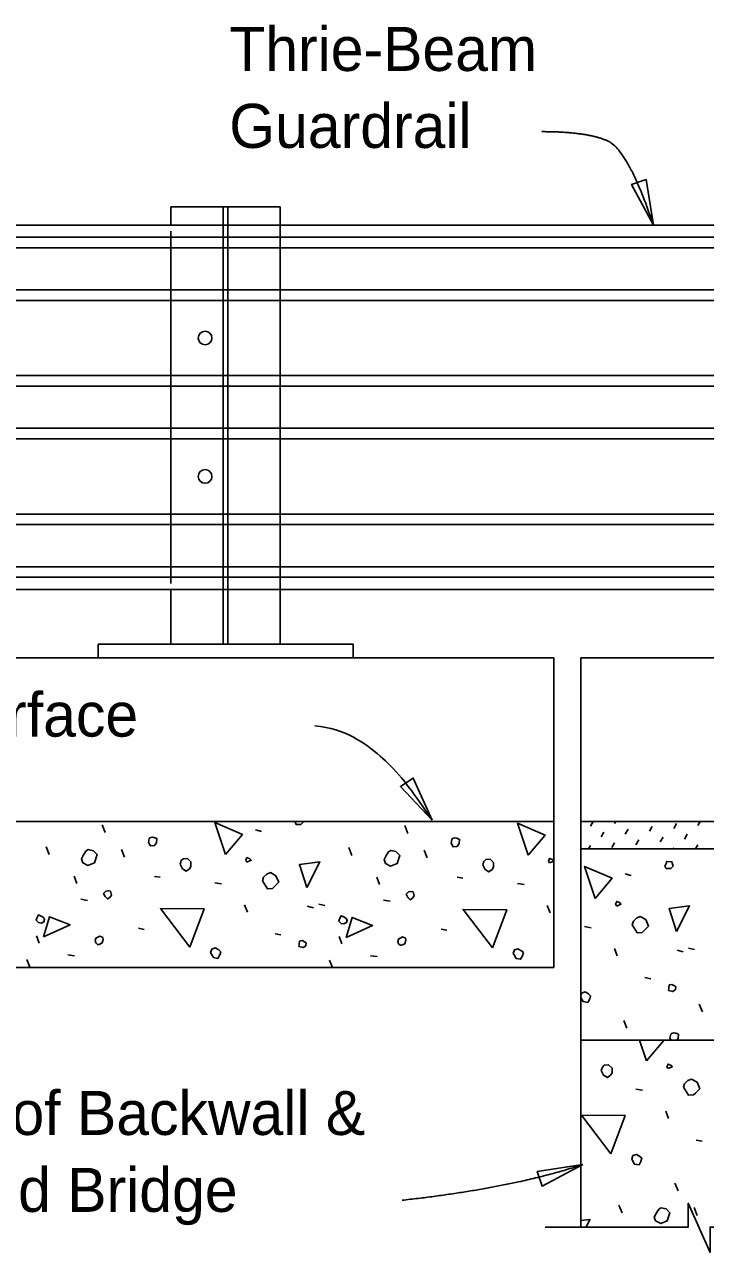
# Model space of a CAD drawing. Extents: x 21587 to 21659.1, y 56116.2 to 56157.3.
# Drawn here: x 21591.41 to 21594.53, y 56132.08 to 56137.7 of the extents above; entities that cross this region are included whole.
import ezdxf

# ---------------------------------------------------------------- set-up
doc = ezdxf.new("R2010")
doc.units = 0
for name, color, linetype in [('AdhocPoint_dp', 7, 'Continuous'), ('Border', 7, 'Continuous'), ('Patterning', 7, 'Continuous'), ('PlotBorder_dp', 7, 'Continuous'), ('SheetBorder_dp', 7, 'Continuous'), ('TextMisc', 7, 'Continuous')]:
    doc.layers.add(name, color=color, linetype=linetype)

msp = doc.modelspace()

# ---------------------------------------------------------------- linework, layer by layer
at = {"layer": 'AdhocPoint_dp'}
for p, q in [((21593.837, 56134.8009), (21587.6633, 56134.8009)), ((21593.837, 56134.8009), (21593.837, 56133.3842)), ((21593.9596, 56134.801), (21593.9596, 56132.1963)), ((21593.9596, 56134.8009), (21601.9067, 56134.8009)), ((21587.6633, 56134.0511), (21593.837, 56134.0511)), ((21604.323, 56134.0511), (21593.9596, 56134.0511)), ((21593.9596, 56133.926), (21604.323, 56133.926)), ((21587.6633, 56133.3843), (21593.837, 56133.3843)), ((21594.9595, 56133.051), (21593.9595, 56133.051))]:
    msp.add_line(p, q, dxfattribs=at)
at = {"layer": 'Border'}
for p, q in [((21592.0846, 56136.8635), (21592.5846, 56136.8635)), ((21592.0846, 56136.8635), (21592.0846, 56136.7802)), ((21592.5846, 56136.8635), (21592.5846, 56136.7802)), ((21599.7592, 56136.7801), (21587.6633, 56136.7801)), ((21587.6633, 56136.7246), (21599.7592, 56136.7246)), ((21587.6633, 56136.6764), (21599.7592, 56136.6764)), ((21587.6633, 56136.4835), (21599.7592, 56136.4835)), ((21587.6633, 56136.4353), (21599.7592, 56136.4353)), ((21587.6633, 56136.0914), (21599.7592, 56136.0914)), ((21587.6633, 56136.0431), (21599.7592, 56136.0431)), ((21587.6633, 56135.8503), (21599.7592, 56135.8503)), ((21587.6633, 56135.8022), (21599.7592, 56135.8022)), ((21587.6633, 56135.4582), (21599.7592, 56135.4582)), ((21587.6633, 56135.41), (21599.7592, 56135.41)), ((21587.6633, 56135.2172), (21599.7592, 56135.2172)), ((21587.6633, 56135.169), (21599.7592, 56135.169)), ((21599.7592, 56135.1134), (21587.6633, 56135.1134)), ((21592.0846, 56135.1135), (21592.0846, 56134.8635)), ((21592.5846, 56135.1134), (21592.5846, 56134.8635)), ((21591.7513, 56134.8635), (21592.9179, 56134.8635)), ((21591.7513, 56134.801), (21591.7513, 56134.8635)), ((21592.0846, 56134.8635), (21592.5846, 56134.8635)), ((21592.9179, 56134.8635), (21592.9179, 56134.801)), ((21591.7513, 56134.801), (21592.9179, 56134.801))]:
    msp.add_line(p, q, dxfattribs=at)
for centre in [(21592.2409, 56136.2634), (21592.2409, 56135.6303)]:
    msp.add_circle(centre, 0.0312, dxfattribs=at)
at = {"layer": 'Patterning'}
for p, q in [((21592.3242, 56134.8635), (21592.3242, 56136.8635)), ((21592.345, 56134.8635), (21592.345, 56136.8635)), ((21592.0846, 56136.7516), (21592.0846, 56135.1398)), ((21592.5846, 56136.7801), (21592.5846, 56135.1134))]:
    msp.add_line(p, q, dxfattribs=at)
at = {"layer": 'PlotBorder_dp'}
for points in [[(21594.2918, 56136.7795), (21594.2594, 56136.9882), (21594.1925, 56136.9659)], [(21593.2795, 56134.0576), (21593.193, 56134.2503), (21593.1343, 56134.2111)], [(21593.9695, 56132.4823), (21593.7607, 56132.4504), (21593.7829, 56132.3835)]]:
    msp.add_lwpolyline(points, close=True, dxfattribs=at)
msp.add_lwpolyline([(21595.248, 56132.1964), (21594.551, 56132.1964), (21594.551, 56132.0802), (21594.4516, 56132.3052), (21594.4516, 56132.1964), (21593.7964, 56132.1964)], dxfattribs=at)
for points, degree in [([(21593.7817, 56137.2074), (21593.9846, 56137.2074), (21594.1766, 56137.1251), (21594.2918, 56136.7795)], 2), ([(21592.7426, 56134.4896), (21592.8844, 56134.4753), (21593.0613, 56134.3451), (21593.1587, 56134.2379), (21593.2794, 56134.0575)], 3), ([(21593.9695, 56132.4824), (21593.6416, 56132.3739), (21593.1426, 56132.319)], 2)]:
    msp.add_open_spline(points, degree=degree, dxfattribs=at)
at = {"layer": 'TextMisc'}
for p, q in [((21594.004, 56134.0297), (21594.0163, 56134.0511)), ((21594.1146, 56134.0427), (21594.1194, 56134.0511)), ((21594.3847, 56134.0198), (21594.3976, 56134.0422)), ((21594.4953, 56134.0328), (21594.5059, 56134.0511)), ((21591.7845, 56134.0008), (21591.7703, 56134.0362)), ((21592.4709, 56134.0132), (21592.4992, 56134.0061)), ((21593.1691, 56133.9973), (21593.155, 56134.0326)), ((21594.0528, 56133.9809), (21594.0658, 56134.0033)), ((21594.1634, 56133.9939), (21594.1764, 56134.0163)), ((21594.2741, 56134.0068), (21594.287, 56134.0292)), ((21594.3229, 56133.958), (21594.3359, 56133.9804)), ((21594.4335, 56133.971), (21594.4465, 56133.9933)), ((21591.5281, 56133.9), (21591.514, 56133.9354)), ((21592.9128, 56133.8965), (21592.8987, 56133.9319)), ((21593.995, 56133.926), (21594.004, 56133.9415)), ((21594.1016, 56133.9321), (21594.1146, 56133.9545)), ((21594.2123, 56133.945), (21594.2252, 56133.9674)), ((21594.3815, 56133.926), (21594.3847, 56133.9315)), ((21594.4846, 56133.926), (21594.4953, 56133.9445)), ((21591.8722, 56133.8883), (21591.8581, 56133.9237)), ((21593.2569, 56133.8848), (21593.2428, 56133.9201)), ((21594.1625, 56133.8122), (21594.1907, 56133.8051)), ((21591.6536, 56133.7675), (21591.6413, 56133.801)), ((21592.0101, 56133.7999), (21592.0349, 56133.7964)), ((21592.2859, 56133.7716), (21592.3159, 56133.7663)), ((21593.0383, 56133.7639), (21593.026, 56133.7975)), ((21593.3948, 56133.7964), (21593.4195, 56133.7928)), ((21593.6706, 56133.7681), (21593.7006, 56133.7628)), ((21591.6725, 56133.6956), (21591.7025, 56133.6903)), ((21592.4344, 56133.6373), (21592.422, 56133.6709)), ((21592.7084, 56133.6638), (21592.7367, 56133.6567)), ((21592.7608, 56133.6738), (21592.7891, 56133.6667)), ((21593.0571, 56133.6921), (21593.0872, 56133.6868)), ((21593.8191, 56133.6337), (21593.8067, 56133.6673)), ((21591.9359, 56133.563), (21591.9624, 56133.5577)), ((21592.5617, 56133.5383), (21592.5882, 56133.533)), ((21593.3205, 56133.5595), (21593.3471, 56133.5542)), ((21593.9775, 56133.5707), (21594.0075, 56133.5654)), ((21591.4822, 56133.4947), (21591.4698, 56133.5283)), ((21592.8669, 56133.4912), (21592.8545, 56133.5248)), ((21591.4397, 56133.3851), (21591.4256, 56133.4205)), ((21591.6124, 56133.4411), (21591.6442, 56133.4375)), ((21592.997, 56133.4375), (21593.0289, 56133.434)), ((21594.126, 56133.4363), (21594.1136, 56133.4699)), ((21594.4, 56133.4628), (21594.4282, 56133.4558)), ((21594.4524, 56133.4728), (21594.4806, 56133.4657)), ((21592.8233, 56133.3843), (21592.8103, 56133.4169)), ((21594.2532, 56133.3373), (21594.2797, 56133.332)), ((21594.516, 56133.1806), (21594.5019, 56133.216)), ((21594.1701, 56133.1057), (21594.156, 56133.1411)), ((21593.9595, 56132.8522), (21593.9611, 56132.8519)), ((21594.2122, 56132.8272), (21594.2422, 56132.8219)), ((21594.3606, 56132.6928), (21594.3483, 56132.7264)), ((21594.4879, 56132.5939), (21594.5144, 56132.5885)), ((21594.4048, 56132.3623), (21594.3907, 56132.3976)), ((21594.1485, 56132.2615), (21594.1344, 56132.2969)), ((21594.4926, 56132.2498), (21594.4785, 56132.2851))]:
    msp.add_line(p, q, dxfattribs=at)
for points in [[(21592.3336, 56133.9007), (21592.2859, 56134.0474), (21592.4114, 56133.9926), (21592.3336, 56133.9007)], [(21592.6533, 56134.0509), (21592.653, 56134.0503), (21592.6583, 56134.0379), (21592.6547, 56134.0415)], [(21592.6583, 56134.0379), (21592.6795, 56134.0379), (21592.6901, 56134.0485), (21592.6894, 56134.0509)], [(21593.7183, 56133.8971), (21593.6706, 56134.0439), (21593.7961, 56133.9891), (21593.7183, 56133.8971)], [(21591.9818, 56133.9555), (21591.9907, 56133.9396), (21592.0101, 56133.9413), (21592.0189, 56133.9537), (21592.0207, 56133.9731), (21592.0083, 56133.9785), (21591.9995, 56133.9802), (21591.9889, 56133.9767), (21591.9854, 56133.9731), (21591.9818, 56133.9555)], [(21593.3665, 56133.9519), (21593.3753, 56133.936), (21593.3948, 56133.9378), (21593.4036, 56133.9502), (21593.4054, 56133.9696), (21593.393, 56133.9749), (21593.3842, 56133.9767), (21593.3736, 56133.9731), (21593.37, 56133.9696), (21593.3665, 56133.9519)], [(21591.6819, 56133.8629), (21591.7049, 56133.8505), (21591.735, 56133.8629), (21591.7473, 56133.9), (21591.7297, 56133.9177), (21591.7067, 56133.923), (21591.6961, 56133.916), (21591.6837, 56133.8965), (21591.6749, 56133.8806), (21591.6819, 56133.8629)], [(21592.1268, 56133.8565), (21592.1374, 56133.8353), (21592.1551, 56133.8247), (21592.1692, 56133.8353), (21592.1763, 56133.8459), (21592.1763, 56133.8671), (21592.1604, 56133.883), (21592.1409, 56133.8812), (21592.1321, 56133.8724), (21592.1268, 56133.8565)], [(21592.4326, 56133.8653), (21592.4521, 56133.8742), (21592.445, 56133.8812), (21592.4326, 56133.8865), (21592.4273, 56133.8742), (21592.4326, 56133.8653)], [(21593.0666, 56133.8594), (21593.0896, 56133.847), (21593.1196, 56133.8594), (21593.132, 56133.8965), (21593.1143, 56133.9142), (21593.0914, 56133.9195), (21593.0808, 56133.9124), (21593.0684, 56133.893), (21593.0595, 56133.8771), (21593.0666, 56133.8594)], [(21593.5115, 56133.8529), (21593.5221, 56133.8317), (21593.5397, 56133.8211), (21593.5539, 56133.8317), (21593.561, 56133.8423), (21593.561, 56133.8635), (21593.545, 56133.8795), (21593.5256, 56133.8777), (21593.5168, 56133.8689), (21593.5115, 56133.8529)], [(21593.8173, 56133.8618), (21593.8367, 56133.8706), (21593.8297, 56133.8777), (21593.8173, 56133.883), (21593.812, 56133.8706), (21593.8173, 56133.8618)], [(21594.3498, 56133.837), (21594.371, 56133.837), (21594.3817, 56133.8476), (21594.3764, 56133.867), (21594.3534, 56133.8688), (21594.3498, 56133.8582), (21594.3445, 56133.8493), (21594.3498, 56133.837), (21594.3463, 56133.8405)], [(21592.5033, 56133.7805), (21592.5263, 56133.7433), (21592.5493, 56133.7451), (21592.5581, 56133.7539), (21592.5776, 56133.7734), (21592.5652, 56133.8034), (21592.5404, 56133.8176), (21592.5228, 56133.8105), (21592.5086, 56133.7964), (21592.5033, 56133.7805)], [(21592.706, 56133.7498), (21592.6724, 56133.8541), (21592.7661, 56133.8665), (21592.706, 56133.7498)], [(21594.0252, 56133.6997), (21593.9775, 56133.8464), (21594.103, 56133.7916), (21594.0252, 56133.6997)], [(21591.7838, 56133.708), (21591.7944, 56133.6974), (21591.8051, 56133.7044), (21591.8121, 56133.7151), (21591.8086, 56133.7327), (21591.7997, 56133.7345), (21591.7874, 56133.7327), (21591.7768, 56133.7221), (21591.7838, 56133.708)], [(21593.1685, 56133.7044), (21593.1791, 56133.6938), (21593.1897, 56133.7009), (21593.1968, 56133.7115), (21593.1933, 56133.7292), (21593.1844, 56133.731), (21593.172, 56133.7292), (21593.1614, 56133.7186), (21593.1685, 56133.7044)], [(21592.171, 56133.4764), (21592.0366, 56133.6532), (21592.2364, 56133.6514), (21592.171, 56133.4764)], [(21593.5557, 56133.4729), (21593.4213, 56133.6496), (21593.6211, 56133.6479), (21593.5557, 56133.4729)], [(21594.1242, 56133.6644), (21594.1436, 56133.6732), (21594.1366, 56133.6803), (21594.1242, 56133.6856), (21594.1189, 56133.6732), (21594.1242, 56133.6644)], [(21594.3976, 56133.5488), (21594.364, 56133.6531), (21594.4577, 56133.6655), (21594.3976, 56133.5488)], [(21591.4786, 56133.5889), (21591.491, 56133.5871), (21591.5034, 56133.5925), (21591.5069, 56133.6031), (21591.5016, 56133.6119), (21591.491, 56133.619), (21591.4786, 56133.6243), (21591.4716, 56133.6101), (21591.468, 56133.5995), (21591.4786, 56133.5889)], [(21591.501, 56133.5241), (21591.5293, 56133.6161), (21591.623, 56133.5789), (21591.501, 56133.5241)], [(21592.8633, 56133.5854), (21592.8757, 56133.5836), (21592.8881, 56133.5889), (21592.8916, 56133.5995), (21592.8863, 56133.6084), (21592.8757, 56133.6154), (21592.8633, 56133.6207), (21592.8562, 56133.6066), (21592.8527, 56133.596), (21592.8633, 56133.5854)], [(21592.8857, 56133.5206), (21592.914, 56133.6125), (21593.0076, 56133.5754), (21592.8857, 56133.5206)], [(21594.1949, 56133.5795), (21594.2179, 56133.5424), (21594.2409, 56133.5441), (21594.2497, 56133.553), (21594.2691, 56133.5724), (21594.2568, 56133.6025), (21594.232, 56133.6166), (21594.2143, 56133.6096), (21594.2002, 56133.5954), (21594.1949, 56133.5795)], [(21591.7485, 56133.4888), (21591.7556, 56133.4888), (21591.7697, 56133.4959), (21591.775, 56133.5118), (21591.7732, 56133.5206), (21591.7591, 56133.5277), (21591.7414, 56133.5171), (21591.7379, 56133.5065), (21591.7414, 56133.4959), (21591.7485, 56133.4888)], [(21592.6695, 56133.4799), (21592.6889, 56133.4746), (21592.7013, 56133.4835), (21592.7031, 56133.4959), (21592.6995, 56133.4994), (21592.6854, 56133.5065), (21592.673, 56133.5047), (21592.6713, 56133.4923), (21592.6695, 56133.4799)], [(21593.1332, 56133.4852), (21593.1402, 56133.4852), (21593.1544, 56133.4923), (21593.1597, 56133.5082), (21593.1579, 56133.5171), (21593.1438, 56133.5241), (21593.1261, 56133.5135), (21593.1226, 56133.5029), (21593.1261, 56133.4923), (21593.1332, 56133.4852)], [(21592.27, 56133.4446), (21592.2788, 56133.4287), (21592.3, 56133.4251), (21592.3089, 56133.4411), (21592.3124, 56133.4552), (21592.3036, 56133.464), (21592.2877, 56133.4729), (21592.2717, 56133.4676), (21592.2664, 56133.4517), (21592.27, 56133.4446)], [(21593.6546, 56133.4411), (21593.6635, 56133.4251), (21593.6847, 56133.4216), (21593.6935, 56133.4375), (21593.6971, 56133.4517), (21593.6882, 56133.4605), (21593.6723, 56133.4693), (21593.6564, 56133.464), (21593.6511, 56133.4481), (21593.6546, 56133.4411)], [(21593.9616, 56133.2436), (21593.9704, 56133.2277), (21593.9916, 56133.2242), (21594.0004, 56133.2401), (21594.004, 56133.2542), (21593.9951, 56133.2631), (21593.9792, 56133.2719), (21593.9633, 56133.2666), (21593.9595, 56133.2553)], [(21594.3611, 56133.279), (21594.3805, 56133.2737), (21594.3929, 56133.2825), (21594.3947, 56133.2949), (21594.3911, 56133.2984), (21594.377, 56133.3055), (21594.3646, 56133.3037), (21594.3628, 56133.2914), (21594.3611, 56133.279)], [(21593.9595, 56133.2476), (21593.9616, 56133.2436)], [(21594.3992, 56133.051), (21594.4046, 56133.0586), (21594.4064, 56133.0781), (21594.394, 56133.0834), (21594.3852, 56133.0851), (21594.3746, 56133.0816), (21594.371, 56133.0781), (21594.3675, 56133.0604)], [(21594.2599, 56132.9562), (21594.2291, 56133.051)], [(21594.3312, 56133.051), (21594.3377, 56133.0482), (21594.2599, 56132.9562)], [(21594.3675, 56133.0604), (21594.3728, 56133.051)], [(21594.0531, 56132.912), (21594.0637, 56132.8908), (21594.0813, 56132.8802), (21594.0955, 56132.8908), (21594.1026, 56132.9014), (21594.1026, 56132.9227), (21594.0866, 56132.9386), (21594.0672, 56132.9368), (21594.0584, 56132.928), (21594.0531, 56132.912)], [(21594.3589, 56132.9209), (21594.3783, 56132.9297), (21594.3713, 56132.9368), (21594.3589, 56132.9421), (21594.3536, 56132.9297), (21594.3589, 56132.9209)], [(21594.4296, 56132.836), (21594.4526, 56132.7989), (21594.4756, 56132.8007), (21594.4844, 56132.8095), (21594.5038, 56132.829), (21594.4915, 56132.859), (21594.4667, 56132.8732), (21594.449, 56132.8661), (21594.4349, 56132.8519), (21594.4296, 56132.836)], [(21594.0972, 56132.532), (21593.9629, 56132.7088), (21594.1627, 56132.707), (21594.0972, 56132.532)], [(21594.1962, 56132.5002), (21594.2051, 56132.4842), (21594.2263, 56132.4807), (21594.2351, 56132.4966), (21594.2387, 56132.5108), (21594.2298, 56132.5196), (21594.2139, 56132.5284), (21594.198, 56132.5231), (21594.1927, 56132.5072), (21594.1962, 56132.5002)], [(21594.3023, 56132.2244), (21594.3253, 56132.212), (21594.3553, 56132.2244), (21594.3677, 56132.2615), (21594.35, 56132.2792), (21594.3271, 56132.2845), (21594.3165, 56132.2774), (21594.3041, 56132.258), (21594.2952, 56132.2421), (21594.3023, 56132.2244)], [(21593.9596, 56132.2259), (21594.0018, 56132.2315), (21593.9837, 56132.1963)]]:
    msp.add_lwpolyline(points, dxfattribs=at)

# ---------------------------------------------------------------- texts
at = {"layer": 'PlotBorder_dp'}
for s, p in [('Thrie-Beam ', (21592.3515, 56137.485)), ('Guardrail', (21592.3515, 56137.133)), ('Front Face of Backwall &', (21589.9768, 56132.6176)), ('Begin or End Bridge', (21589.9768, 56132.2656))]:
    msp.add_text(s, height=0.2016, dxfattribs=at).set_placement(p)
at = {"layer": 'SheetBorder_dp'}
msp.add_text('Final Riding Surface', height=0.2016, dxfattribs=at).set_placement((21589.5074, 56134.4399))

doc.saveas('drawing.dxf')
